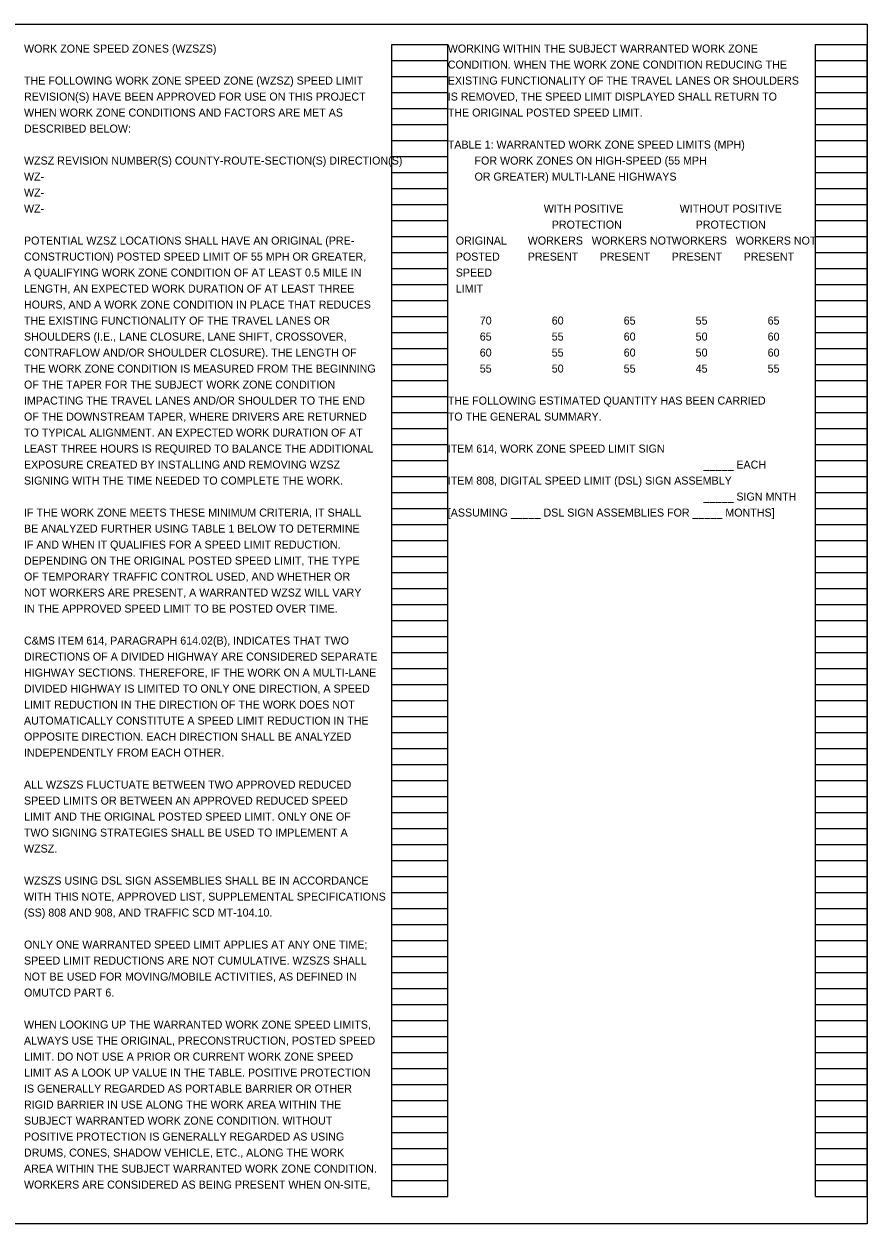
# Model space of a CAD drawing. Extents: x -34 to 2132911, y 0 to 658646.
# Drawn here: x 17.24 to 32, y 0.5 to 21.5 of the extents above; entities that cross this region are included whole.
import ezdxf

# ---------------------------------------------------------------- set-up
doc = ezdxf.new("R2010")
doc.units = 0
for name, color, linetype in [('SC_Scratch1', 7, 'Continuous'), ('SH_Data', 7, 'Continuous'), ('SH_Text', 7, 'Continuous')]:
    doc.layers.add(name, color=color, linetype=linetype)

msp = doc.modelspace()

# ---------------------------------------------------------------- linework, layer by layer
at = {"layer": 'SC_Scratch1'}
msp.add_lwpolyline([(1.5, 21.5), (32, 21.5), (32, 0.5), (1.5, 0.5)], close=True, dxfattribs=at)
at = {"layer": 'SH_Data'}
for p, q in [((23.68, 0.98), (23.68, 21.14)), ((23.68, 21.14), (24.66, 21.14)), ((24.66, 0.98), (24.66, 21.14)), ((31.1, 0.98), (31.1, 21.14)), ((31.1, 21.14), (32, 21.14)), ((32, 0.98), (32, 21.14)), ((23.68, 20.86), (24.66, 20.86)), ((31.1, 20.86), (32, 20.86)), ((23.68, 20.58), (24.66, 20.58)), ((31.1, 20.58), (32, 20.58)), ((23.68, 20.3), (24.66, 20.3)), ((31.1, 20.3), (32, 20.3)), ((23.68, 20.02), (24.66, 20.02)), ((31.1, 20.02), (32, 20.02)), ((23.68, 19.74), (24.66, 19.74)), ((31.1, 19.74), (32, 19.74)), ((23.68, 19.46), (24.66, 19.46)), ((31.1, 19.46), (32, 19.46)), ((23.68, 19.18), (24.66, 19.18)), ((31.1, 19.18), (32, 19.18)), ((23.68, 18.9), (24.66, 18.9)), ((31.1, 18.9), (32, 18.9)), ((23.68, 18.62), (24.66, 18.62)), ((31.1, 18.62), (32, 18.62)), ((23.68, 18.34), (24.66, 18.34)), ((31.1, 18.34), (32, 18.34)), ((23.68, 18.06), (24.66, 18.06)), ((31.1, 18.06), (32, 18.06)), ((23.68, 17.78), (24.66, 17.78)), ((31.1, 17.78), (32, 17.78)), ((23.68, 17.5), (24.66, 17.5)), ((31.1, 17.5), (32, 17.5)), ((23.68, 17.22), (24.66, 17.22)), ((31.1, 17.22), (32, 17.22)), ((23.68, 16.94), (24.66, 16.94)), ((31.1, 16.94), (32, 16.94)), ((23.68, 16.66), (24.66, 16.66)), ((31.1, 16.66), (32, 16.66)), ((23.68, 16.38), (24.66, 16.38)), ((31.1, 16.38), (32, 16.38)), ((23.68, 16.1), (24.66, 16.1)), ((31.1, 16.1), (32, 16.1)), ((23.68, 15.82), (24.66, 15.82)), ((31.1, 15.82), (32, 15.82)), ((23.68, 15.54), (24.66, 15.54)), ((31.1, 15.54), (32, 15.54)), ((23.68, 15.26), (24.66, 15.26)), ((31.1, 15.26), (32, 15.26)), ((23.68, 14.98), (24.66, 14.98)), ((31.1, 14.98), (32, 14.98)), ((23.68, 14.7), (24.66, 14.7)), ((31.1, 14.7), (32, 14.7)), ((23.68, 14.42), (24.66, 14.42)), ((31.1, 14.42), (32, 14.42)), ((23.68, 14.14), (24.66, 14.14)), ((31.1, 14.14), (32, 14.14)), ((23.68, 13.86), (24.66, 13.86)), ((31.1, 13.86), (32, 13.86)), ((23.68, 13.58), (24.66, 13.58)), ((31.1, 13.58), (32, 13.58)), ((23.68, 13.3), (24.66, 13.3)), ((31.1, 13.3), (32, 13.3)), ((23.68, 13.02), (24.66, 13.02)), ((31.1, 13.02), (32, 13.02)), ((23.68, 12.74), (24.66, 12.74)), ((31.1, 12.74), (32, 12.74)), ((23.68, 12.46), (24.66, 12.46)), ((31.1, 12.46), (32, 12.46)), ((23.68, 12.18), (24.66, 12.18)), ((31.1, 12.18), (32, 12.18)), ((23.68, 11.9), (24.66, 11.9)), ((31.1, 11.9), (32, 11.9)), ((23.68, 11.62), (24.66, 11.62)), ((31.1, 11.62), (32, 11.62)), ((23.68, 11.34), (24.66, 11.34)), ((31.1, 11.34), (32, 11.34)), ((23.68, 11.06), (24.66, 11.06)), ((31.1, 11.06), (32, 11.06)), ((23.68, 10.78), (24.66, 10.78)), ((31.1, 10.78), (32, 10.78)), ((23.68, 10.5), (24.66, 10.5)), ((31.1, 10.5), (32, 10.5)), ((23.68, 10.22), (24.66, 10.22)), ((31.1, 10.22), (32, 10.22)), ((23.68, 9.94), (24.66, 9.94)), ((31.1, 9.94), (32, 9.94)), ((23.68, 9.66), (24.66, 9.66)), ((31.1, 9.66), (32, 9.66)), ((23.68, 9.38), (24.66, 9.38)), ((31.1, 9.38), (32, 9.38)), ((23.68, 9.1), (24.66, 9.1)), ((31.1, 9.1), (32, 9.1)), ((23.68, 8.82), (24.66, 8.82)), ((31.1, 8.82), (32, 8.82)), ((23.68, 8.54), (24.66, 8.54)), ((31.1, 8.54), (32, 8.54)), ((23.68, 8.26), (24.66, 8.26)), ((31.1, 8.26), (32, 8.26)), ((23.68, 7.98), (24.66, 7.98)), ((31.1, 7.98), (32, 7.98)), ((23.68, 7.7), (24.66, 7.7)), ((31.1, 7.7), (32, 7.7)), ((23.68, 7.42), (24.66, 7.42)), ((31.1, 7.42), (32, 7.42)), ((23.68, 7.14), (24.66, 7.14)), ((31.1, 7.14), (32, 7.14)), ((23.68, 6.86), (24.66, 6.86)), ((31.1, 6.86), (32, 6.86)), ((23.68, 6.58), (24.66, 6.58)), ((31.1, 6.58), (32, 6.58)), ((23.68, 6.3), (24.66, 6.3)), ((31.1, 6.3), (32, 6.3)), ((23.68, 6.02), (24.66, 6.02)), ((31.1, 6.02), (32, 6.02)), ((23.68, 5.74), (24.66, 5.74)), ((31.1, 5.74), (32, 5.74)), ((23.68, 5.46), (24.66, 5.46)), ((31.1, 5.46), (32, 5.46)), ((23.68, 5.18), (24.66, 5.18)), ((31.1, 5.18), (32, 5.18)), ((23.68, 4.9), (24.66, 4.9)), ((31.1, 4.9), (32, 4.9)), ((23.68, 4.62), (24.66, 4.62)), ((31.1, 4.62), (32, 4.62)), ((23.68, 4.34), (24.66, 4.34)), ((31.1, 4.34), (32, 4.34)), ((23.68, 4.06), (24.66, 4.06)), ((31.1, 4.06), (32, 4.06)), ((23.68, 3.78), (24.66, 3.78)), ((31.1, 3.78), (32, 3.78)), ((23.68, 3.5), (24.66, 3.5)), ((31.1, 3.5), (32, 3.5)), ((23.68, 3.22), (24.66, 3.22)), ((31.1, 3.22), (32, 3.22)), ((23.68, 2.94), (24.66, 2.94)), ((31.1, 2.94), (32, 2.94)), ((23.68, 2.66), (24.66, 2.66)), ((31.1, 2.66), (32, 2.66)), ((23.68, 2.38), (24.66, 2.38)), ((31.1, 2.38), (32, 2.38)), ((23.68, 2.1), (24.66, 2.1)), ((31.1, 2.1), (32, 2.1)), ((23.68, 1.82), (24.66, 1.82)), ((31.1, 1.82), (32, 1.82)), ((23.68, 1.54), (24.66, 1.54)), ((31.1, 1.54), (32, 1.54)), ((23.68, 1.26), (24.66, 1.26)), ((31.1, 1.26), (32, 1.26)), ((23.68, 0.98), (24.66, 0.98)), ((31.1, 0.98), (32, 0.98))]:
    msp.add_line(p, q, dxfattribs=at)

# ---------------------------------------------------------------- texts
at = {"layer": 'SH_Text'}
for s, p in [('WORK ZONE SPEED ZONES (WZSZS)', (17.24, 21)), ('WORKING WITHIN THE SUBJECT WARRANTED WORK ZONE', (24.66, 21)), ('CONDITION. WHEN THE WORK ZONE CONDITION REDUCING THE', (24.66, 20.72)), ('THE FOLLOWING WORK ZONE SPEED ZONE (WZSZ) SPEED LIMIT', (17.24, 20.44)), ('EXISTING FUNCTIONALITY OF THE TRAVEL LANES OR SHOULDERS', (24.66, 20.44)), ('REVISION(S) HAVE BEEN APPROVED FOR USE ON THIS PROJECT', (17.24, 20.16)), ('IS REMOVED, THE SPEED LIMIT DISPLAYED SHALL RETURN TO', (24.66, 20.16)), ('WHEN WORK ZONE CONDITIONS AND FACTORS ARE MET AS', (17.24, 19.88)), ('THE ORIGINAL POSTED SPEED LIMIT.', (24.66, 19.88)), ('DESCRIBED BELOW:', (17.24, 19.6)), ('TABLE 1: WARRANTED WORK ZONE SPEED LIMITS (MPH)', (24.66, 19.32)), ('WZSZ REVISION NUMBER(S) COUNTY-ROUTE-SECTION(S) DIRECTION(S)', (17.24, 19.04)), ('         FOR WORK ZONES ON HIGH-SPEED (55 MPH', (24.66, 19.04)), ('WZ-', (17.24, 18.76)), ('         OR GREATER) MULTI-LANE HIGHWAYS', (24.66, 18.76)), ('WZ-', (17.24, 18.48)), ('WZ-', (17.24, 18.2)), ('WITH POSITIVE    ', (26.34, 18.2)), ('WITHOUT POSITIVE', (28.72, 18.2)), ('PROTECTION        ', (26.48, 17.92)), ('PROTECTION', (29, 17.92)), ('POTENTIAL WZSZ LOCATIONS SHALL HAVE AN ORIGINAL (PRE-', (17.24, 17.64)), ('ORIGINAL    ', (24.8, 17.64)), ('WORKERS', (26.06, 17.64)), ('WORKERS NOT', (27.18, 17.64)), ('WORKERS', (28.58, 17.64)), ('WORKERS NOT', (29.7, 17.64)), ('CONSTRUCTION) POSTED SPEED LIMIT OF 55 MPH OR GREATER,', (17.24, 17.36)), ('POSTED     ', (24.8, 17.36)), ('PRESENT  ', (26.06, 17.36)), ('PRESENT ', (27.32, 17.36)), ('PRESENT  ', (28.58, 17.36)), ('PRESENT', (29.84, 17.36)), ('A QUALIFYING WORK ZONE CONDITION OF AT LEAST 0.5 MILE IN', (17.24, 17.08)), ('SPEED', (24.8, 17.08)), ('LENGTH, AN EXPECTED WORK DURATION OF AT LEAST THREE', (17.24, 16.8)), ('LIMIT', (24.8, 16.8)), ('HOURS, AND A WORK ZONE CONDITION IN PLACE THAT REDUCES', (17.24, 16.52)), ('THE EXISTING FUNCTIONALITY OF THE TRAVEL LANES OR', (17.24, 16.24)), ('70         ', (25.22, 16.24)), ('60        ', (26.48, 16.24)), ('65           ', (27.74, 16.24)), ('55       ', (29, 16.24)), ('65', (30.26, 16.24)), ('SHOULDERS (I.E., LANE CLOSURE, LANE SHIFT, CROSSOVER,', (17.24, 15.96)), ('65         ', (25.22, 15.96)), ('55        ', (26.48, 15.96)), ('60            ', (27.74, 15.96)), ('50       ', (29, 15.96)), ('60', (30.26, 15.96)), ('CONTRAFLOW AND/OR SHOULDER CLOSURE). THE LENGTH OF', (17.24, 15.68)), ('60         ', (25.22, 15.68)), ('55        ', (26.48, 15.68)), ('60            ', (27.74, 15.68)), ('50       ', (29, 15.68)), ('60', (30.26, 15.68)), ('THE WORK ZONE CONDITION IS MEASURED FROM THE BEGINNING', (17.24, 15.4)), ('50        ', (26.48, 15.4)), ('55         ', (25.22, 15.4)), ('55            ', (27.74, 15.4)), ('45       ', (29, 15.4)), ('55', (30.26, 15.4)), ('OF THE TAPER FOR THE SUBJECT WORK ZONE CONDITION', (17.24, 15.12)), ('IMPACTING THE TRAVEL LANES AND/OR SHOULDER TO THE END', (17.24, 14.84)), ('THE FOLLOWING ESTIMATED QUANTITY HAS BEEN CARRIED', (24.66, 14.84)), ('OF THE DOWNSTREAM TAPER, WHERE DRIVERS ARE RETURNED', (17.24, 14.56)), ('TO THE GENERAL SUMMARY.', (24.66, 14.56)), ('TO TYPICAL ALIGNMENT. AN EXPECTED WORK DURATION OF AT', (17.24, 14.28)), ('LEAST THREE HOURS IS REQUIRED TO BALANCE THE ADDITIONAL', (17.24, 14)), ('ITEM 614, WORK ZONE SPEED LIMIT SIGN', (24.66, 14)), ('EXPOSURE CREATED BY INSTALLING AND REMOVING WZSZ', (17.24, 13.72)), ('_____ EACH', (29.14, 13.72)), ('SIGNING WITH THE TIME NEEDED TO COMPLETE THE WORK.', (17.24, 13.44)), ('ITEM 808, DIGITAL SPEED LIMIT (DSL) SIGN ASSEMBLY', (24.66, 13.44)), ('_____ SIGN MNTH', (29.14, 13.16)), ('IF THE WORK ZONE MEETS THESE MINIMUM CRITERIA, IT SHALL', (17.24, 12.88)), ('[ASSUMING _____ DSL SIGN ASSEMBLIES FOR _____ MONTHS]', (24.66, 12.88)), ('BE ANALYZED FURTHER USING TABLE 1 BELOW TO DETERMINE', (17.24, 12.6)), ('IF AND WHEN IT QUALIFIES FOR A SPEED LIMIT REDUCTION.', (17.24, 12.32)), ('DEPENDING ON THE ORIGINAL POSTED SPEED LIMIT, THE TYPE', (17.24, 12.04)), ('OF TEMPORARY TRAFFIC CONTROL USED, AND WHETHER OR', (17.24, 11.76)), ('NOT WORKERS ARE PRESENT, A WARRANTED WZSZ WILL VARY', (17.24, 11.48)), ('IN THE APPROVED SPEED LIMIT TO BE POSTED OVER TIME.', (17.24, 11.2)), ('C&MS ITEM 614, PARAGRAPH 614.02(B), INDICATES THAT TWO', (17.24, 10.64)), ('DIRECTIONS OF A DIVIDED HIGHWAY ARE CONSIDERED SEPARATE', (17.24, 10.36)), ('HIGHWAY SECTIONS. THEREFORE, IF THE WORK ON A MULTI-LANE', (17.24, 10.08)), ('DIVIDED HIGHWAY IS LIMITED TO ONLY ONE DIRECTION, A SPEED', (17.24, 9.8)), ('LIMIT REDUCTION IN THE DIRECTION OF THE WORK DOES NOT', (17.24, 9.52)), ('AUTOMATICALLY CONSTITUTE A SPEED LIMIT REDUCTION IN THE', (17.24, 9.24)), ('OPPOSITE DIRECTION. EACH DIRECTION SHALL BE ANALYZED', (17.24, 8.96)), ('INDEPENDENTLY FROM EACH OTHER.', (17.24, 8.68)), ('ALL WZSZS FLUCTUATE BETWEEN TWO APPROVED REDUCED', (17.24, 8.12)), ('SPEED LIMITS OR BETWEEN AN APPROVED REDUCED SPEED', (17.24, 7.84)), ('LIMIT AND THE ORIGINAL POSTED SPEED LIMIT. ONLY ONE OF', (17.24, 7.56)), ('TWO SIGNING STRATEGIES SHALL BE USED TO IMPLEMENT A', (17.24, 7.28)), ('WZSZ.', (17.24, 7)), ('WZSZS USING DSL SIGN ASSEMBLIES SHALL BE IN ACCORDANCE', (17.24, 6.44)), ('WITH THIS NOTE, APPROVED LIST, SUPPLEMENTAL SPECIFICATIONS', (17.24, 6.16)), ('(SS) 808 AND 908, AND TRAFFIC SCD MT-104.10.', (17.24, 5.88)), ('ONLY ONE WARRANTED SPEED LIMIT APPLIES AT ANY ONE TIME;', (17.24, 5.32)), ('SPEED LIMIT REDUCTIONS ARE NOT CUMULATIVE. WZSZS SHALL', (17.24, 5.04)), ('NOT BE USED FOR MOVING/MOBILE ACTIVITIES, AS DEFINED IN', (17.24, 4.76)), ('OMUTCD PART 6.', (17.24, 4.48)), ('WHEN LOOKING UP THE WARRANTED WORK ZONE SPEED LIMITS,', (17.24, 3.92)), ('ALWAYS USE THE ORIGINAL, PRECONSTRUCTION, POSTED SPEED', (17.24, 3.64)), ('LIMIT. DO NOT USE A PRIOR OR CURRENT WORK ZONE SPEED', (17.24, 3.36)), ('LIMIT AS A LOOK UP VALUE IN THE TABLE. POSITIVE PROTECTION', (17.24, 3.08)), ('IS GENERALLY REGARDED AS PORTABLE BARRIER OR OTHER', (17.24, 2.8)), ('RIGID BARRIER IN USE ALONG THE WORK AREA WITHIN THE', (17.24, 2.52)), ('SUBJECT WARRANTED WORK ZONE CONDITION. WITHOUT', (17.24, 2.24)), ('POSITIVE PROTECTION IS GENERALLY REGARDED AS USING', (17.24, 1.96)), ('DRUMS, CONES, SHADOW VEHICLE, ETC., ALONG THE WORK', (17.24, 1.68)), ('AREA WITHIN THE SUBJECT WARRANTED WORK ZONE CONDITION.', (17.24, 1.4)), ('WORKERS ARE CONSIDERED AS BEING PRESENT WHEN ON-SITE,', (17.24, 1.12))]:
    msp.add_text(s, height=0.14, dxfattribs=at).set_placement(p)

doc.saveas('drawing.dxf')
